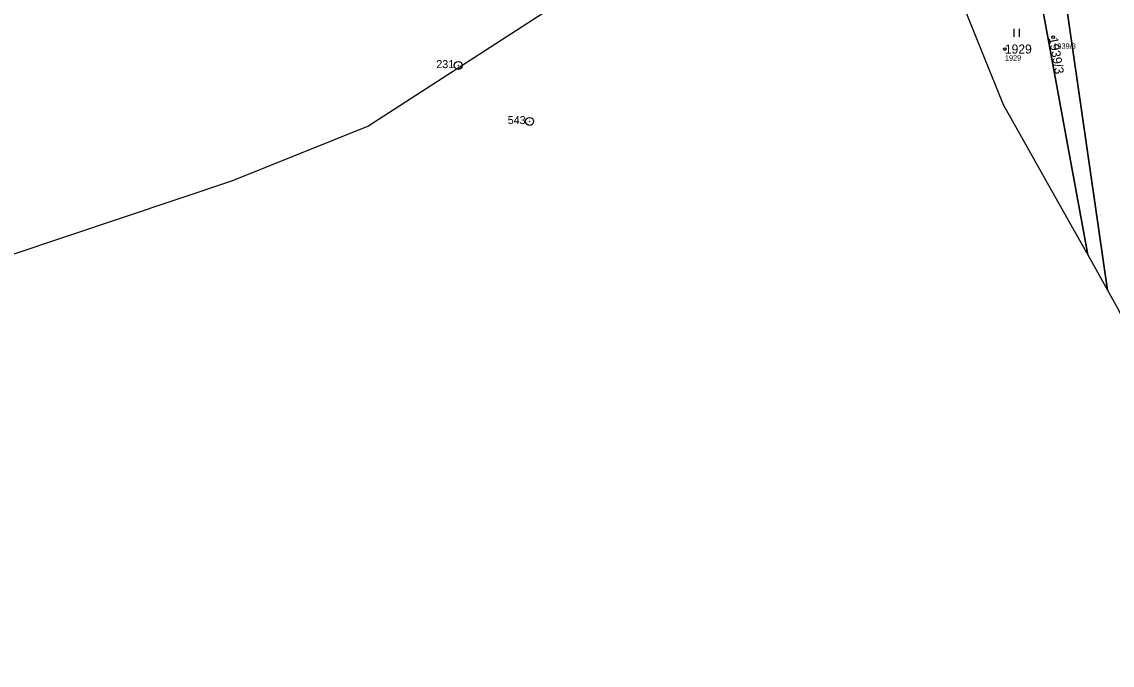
# Model space of a CAD drawing. Extents: x -762274 to -759271, y -1061928 to -1059060.
# Drawn here: x -761545 to -761340.6, y -1061489 to -1061368.3 of the extents above; entities that cross this region are included whole.
import ezdxf

# ---------------------------------------------------------------- set-up
doc = ezdxf.new("R2010")
doc.units = 0
for name, color, linetype in [('Definiční body', 7, 'Continuous'), ('Hranice parcel', 7, 'Continuous'), ('Parcelní čísla', 7, 'Continuous'), ('Polygon ku', 7, 'Continuous'), ('Polygon parcely', 7, 'Continuous'), ('Značky bodu BP', 7, 'Continuous'), ('Značky kultur', 7, 'Continuous')]:
    doc.layers.add(name, color=color, linetype=linetype)

msp = doc.modelspace()

# ---------------------------------------------------------------- linework, layer by layer
at = {"layer": 'Definiční body'}
for centre in [(-761351.6, -1061371.24), (-761360.68, -1061373.45)]:
    msp.add_circle(centre, 0.25, dxfattribs=at)
at = {"layer": 'Hranice parcel'}
for p, q in [((-761354.06, -1061363.33), (-761345.14, -1061412.04)), ((-761368.76, -1061364.65), (-761360.99, -1061383.83)), ((-761360.99, -1061383.83), (-761348.56, -1061405.96)), ((-761348.56, -1061405.96), (-761345.14, -1061412.04)), ((-761345.14, -1061412.04), (-761343.64, -1061414.72)), ((-761343.64, -1061414.72), (-761341.44, -1061418.64))]:
    msp.add_line(p, q, dxfattribs=at)
for points in [[(-761577.63, -1061422.31), (-761505.64, -1061398.15), (-761480.14, -1061387.93), (-761430.18, -1061355.61)], [(-761351.14, -1061358.86), (-761349.46, -1061363.22), (-761341.44, -1061418.64)], [(-761341.44, -1061418.64), (-761339.29, -1061422.47), (-761330.52, -1061440.69), (-761329.14, -1061442.9)]]:
    msp.add_lwpolyline(points, dxfattribs=at)
at = {"layer": 'Polygon ku'}
msp.add_lwpolyline([(-761577.63, -1061422.31), (-761505.64, -1061398.15), (-761480.14, -1061387.93), (-761430.18, -1061355.61), (-761410.18, -1061349.61), (-761405.5, -1061350.3), (-761385.02, -1061353.32), (-761378.83, -1061354.23), (-761374.04, -1061354.94), (-761371.18, -1061360.21), (-761369.36, -1061363.54), (-761368.76, -1061364.65), (-761360.99, -1061383.83), (-761348.56, -1061405.96), (-761345.14, -1061412.04), (-761343.64, -1061414.72), (-761341.44, -1061418.64), (-761339.29, -1061422.47), (-761330.52, -1061440.69), (-761329.14, -1061442.9), (-761326.6, -1061448.32), (-761317.85, -1061466.99), (-761312.47, -1061479.91), (-761292.38, -1061534.51)], dxfattribs=at)
at = {"layer": 'Polygon parcely'}
for points in [[(-761405.5, -1061350.3), (-761409.33, -1061340.57), (-761445.5, -1061345.53), (-761469.77, -1061348.28), (-761488.71, -1061351.23), (-761491.16, -1061351.61), (-761509.65, -1061355.89), (-761534.42, -1061362.49), (-761551.25, -1061367.02), (-761569.42, -1061371.94), (-761581.68, -1061375.62), (-761594.4, -1061379.26), (-761627.47, -1061389.54), (-761661.15, -1061403.44), (-761669.83, -1061408.68), (-761678.42, -1061420.88), (-761649.83, -1061423.35), (-761598.9, -1061424.84), (-761577.63, -1061422.31), (-761505.64, -1061398.15), (-761480.14, -1061387.93), (-761430.18, -1061355.61), (-761410.18, -1061349.61)], [(-761313.38, -1061476.97), (-761311.64, -1061459.54), (-761320.93, -1061409.68), (-761327.59, -1061383.82), (-761328.97, -1061358.49), (-761337.3, -1061345.21), (-761342.05, -1061347.93), (-761351.14, -1061358.86), (-761349.46, -1061363.22), (-761341.44, -1061418.64), (-761339.29, -1061422.47), (-761330.52, -1061440.69), (-761329.14, -1061442.9), (-761314.98, -1061456.32)], [(-761343.64, -1061414.72), (-761341.44, -1061418.64), (-761349.46, -1061363.22), (-761351.14, -1061358.86), (-761350.95, -1061353.01), (-761355.4, -1061355.56), (-761354.54, -1061358.97), (-761354.06, -1061363.33), (-761345.14, -1061412.04)], [(-761348.56, -1061405.96), (-761345.14, -1061412.04), (-761354.06, -1061363.33), (-761366.31, -1061364.67), (-761368.76, -1061364.65), (-761360.99, -1061383.83)]]:
    msp.add_lwpolyline(points, close=True, dxfattribs=at)
at = {"layer": 'Značky bodu BP'}
for centre, radius in [((-761463.17, -1061376.53), 0.75), ((-761463.17, -1061376.53), 0.03), ((-761449.78, -1061387.02), 0.75), ((-761449.78, -1061387.02), 0.03)]:
    msp.add_circle(centre, radius, dxfattribs=at)
at = {"layer": 'Značky kultur'}
for p, q in [((-761358.96, -1061371.17), (-761358.96, -1061369.67)), ((-761357.96, -1061371.17), (-761357.96, -1061369.67))]:
    msp.add_line(p, q, dxfattribs=at)

# ---------------------------------------------------------------- texts
at = {"layer": 'Definiční body'}
for s, p in [('1939/3', (-761351.6, -1061373.4)), ('1929', (-761360.68, -1061375.61))]:
    msp.add_text(s, height=1, dxfattribs=at).set_placement(p)
at = {"layer": 'Parcelní čísla'}
msp.add_text('1939/3', height=1.7, rotation=280, dxfattribs=at).set_placement((-761352.44, -1061371.39))
msp.add_text('1929', height=1.7, dxfattribs=at).set_placement((-761360.68, -1061374.3))
at = {"layer": 'Značky bodu BP'}
for s, p in [('231', (-761467.27, -1061377.03)), ('543', (-761453.88, -1061387.52))]:
    msp.add_text(s, height=1.5, dxfattribs=at).set_placement(p)

doc.saveas('drawing.dxf')
